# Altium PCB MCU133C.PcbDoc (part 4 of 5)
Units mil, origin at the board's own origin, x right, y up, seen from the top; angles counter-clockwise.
Board outline 2300 x 5500 mil, 4 copper layers (Top Signal, GND, PWR, Bottom Signal), stack 61.6 mil thick; 278 components, 226 nets, 1057 pads, 868 vias.
Unrouted connection lines stored in the file: 237.
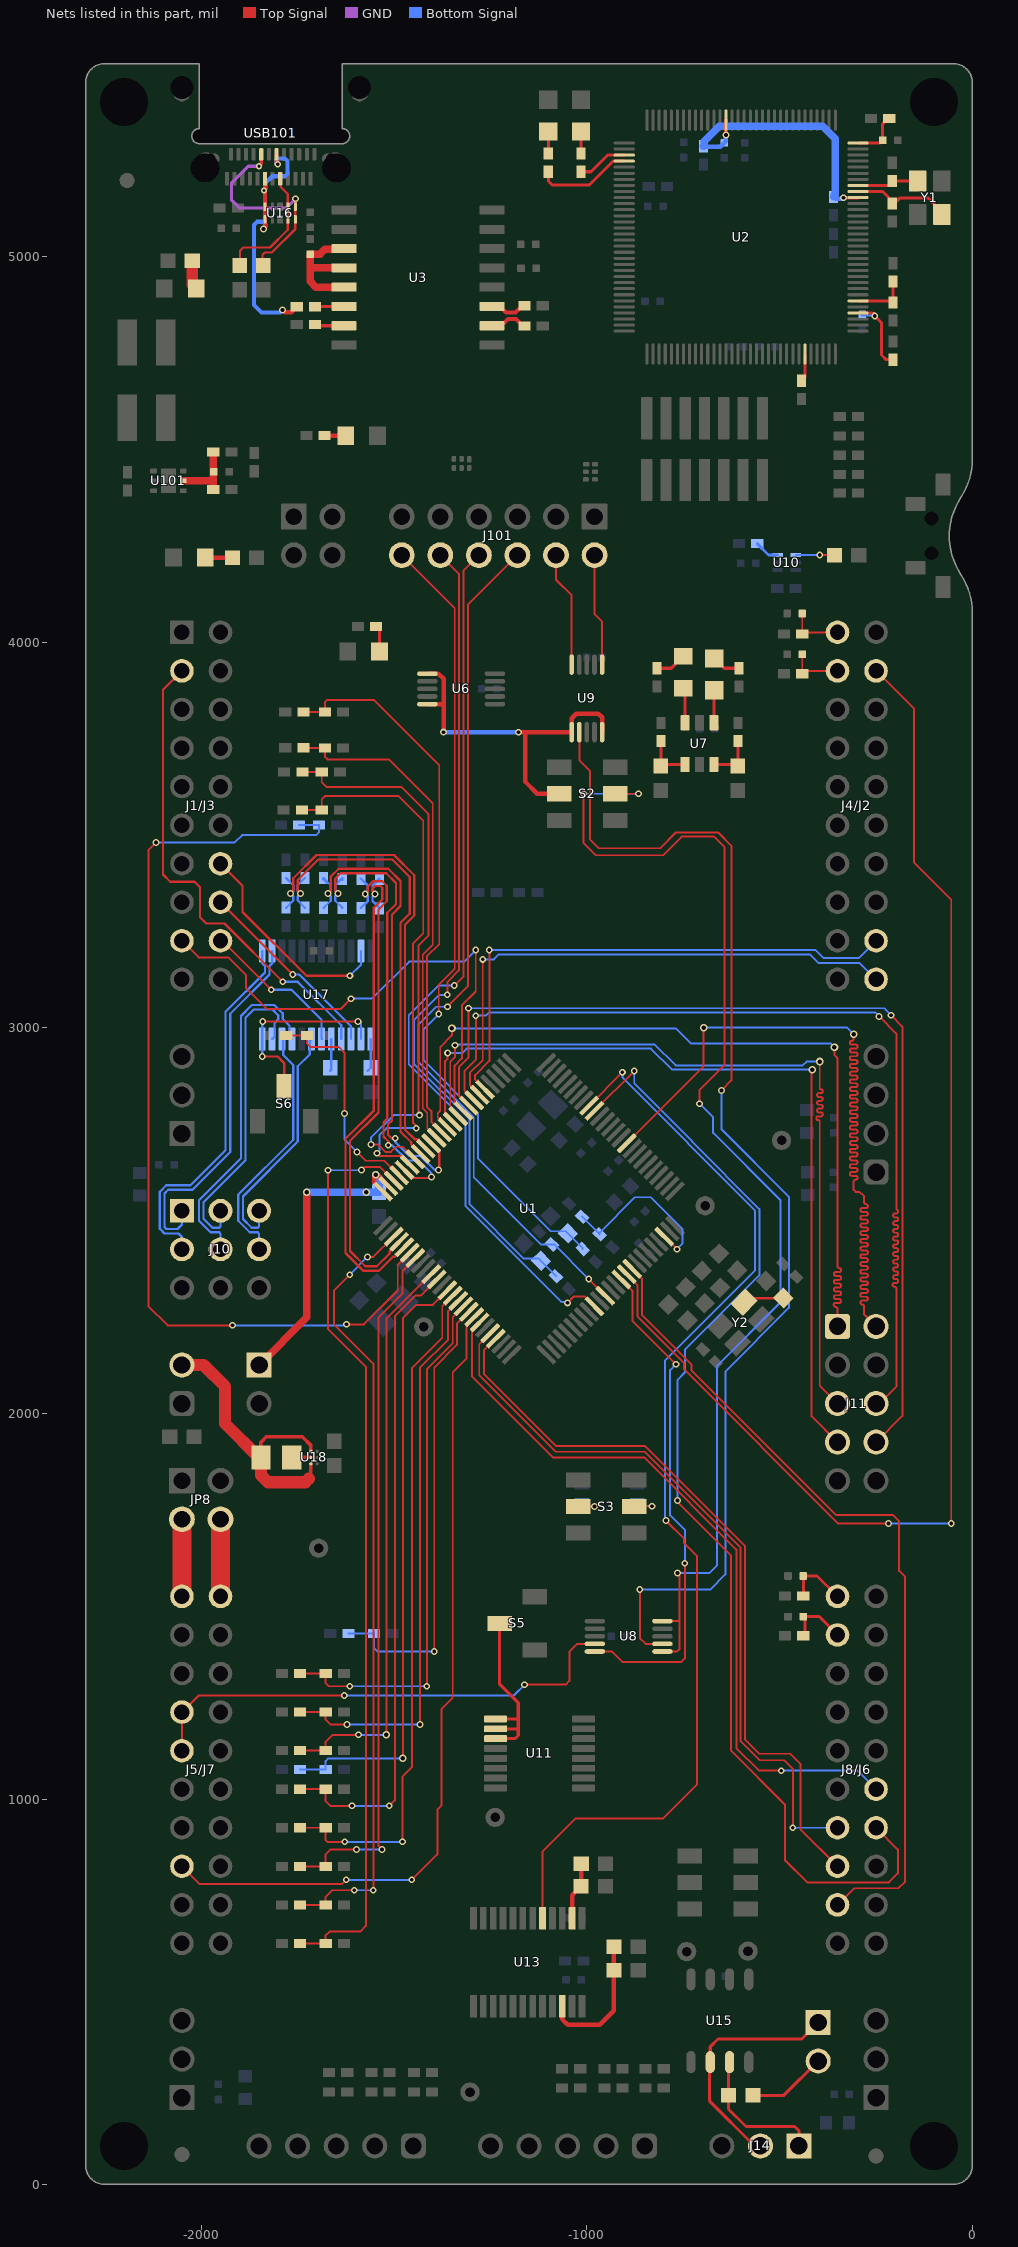
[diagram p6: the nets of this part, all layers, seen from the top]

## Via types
v1: diameter 17.72, hole 9.84, Top Signal to Bottom Signal, tented both sides, 822 vias
v2: diameter 19.68, hole 11.81, Top Signal to Bottom Signal, tented both sides, 22 vias
v3: diameter 27.56, hole 15.75, Top Signal to Bottom Signal, tented both sides, 17 vias
v4: diameter 15.75, hole 7.87, Top Signal to Bottom Signal, tented both sides, 5 vias
v5: diameter 19.68, hole 7.87, Top Signal to Bottom Signal, tented both sides, 2 vias

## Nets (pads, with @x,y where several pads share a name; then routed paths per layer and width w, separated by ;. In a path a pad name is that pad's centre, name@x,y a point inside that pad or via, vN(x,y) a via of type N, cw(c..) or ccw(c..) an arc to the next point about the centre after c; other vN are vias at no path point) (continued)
GPIO44_FSITXCLK: J11.2 U1.85 | length 2524.2
  Top Signal w5: U1.85@-896.72,2700.92 -697.04,2900.6 v2(-697.04,3000.55) ; v2(-308.04,2983.55) -308.04,2975.55 -308.04,2971.22 cw(c-313.04,2971.22) -313.04,2966.22 ccw(c-313.04,2961.22) -318.04,2961.22 ccw(c-313.04,2961.22) -313.04,2956.22 -308.04,2956.22 -303.04,2956.22 cw(c-303.04,2951.22) -298.04,2951.22 cw(c-303.04,2951.22) -303.04,2946.22 -308.04,2946.22 -313.04,2946.22 ccw(c-313.04,2941.22) -318.04,2941.22 ccw(c-313.04,2941.22) -313.04,2936.22 -308.04,2936.22 -303.04,2936.22 cw(c-303.04,2931.22) -298.04,2931.22 cw(c-303.04,2931.22) -303.04,2926.22 -308.04,2926.22 -313.04,2926.22 ccw(c-313.04,2921.22) -318.04,2921.22 ccw(c-313.04,2921.22) -313.04,2916.22 -308.04,2916.22 -303.04,2916.22 cw(c-303.04,2911.22) -298.04,2911.22 cw(c-303.04,2911.22) -303.04,2906.22 -308.04,2906.22 -313.04,2906.22 ccw(c-313.04,2901.22) -318.04,2901.22 ccw(c-313.04,2901.22) -313.04,2896.22 -308.04,2896.22 -303.04,2896.22 cw(c-303.04,2891.22) -298.04,2891.22 cw(c-303.04,2891.22) -303.04,2886.22 -308.04,2886.22 -313.04,2886.22 ccw(c-313.04,2881.22) -318.04,2881.22 ccw(c-313.04,2881.22) -313.04,2876.22 -308.04,2876.22 -303.04,2876.22 cw(c-303.04,2871.22) -298.04,2871.22 cw(c-303.04,2871.22) -303.04,2866.22 -308.04,2866.22 -313.04,2866.22 ccw(c-313.04,2861.22) -318.04,2861.22 ccw(c-313.04,2861.22) -313.04,2856.22 -308.04,2856.22 -303.04,2856.22 cw(c-303.04,2851.22) -298.04,2851.22 cw(c-303.04,2851.22) -303.04,2846.22 -308.04,2846.22 -313.04,2846.22 ccw(c-313.04,2841.22) -318.04,2841.22 ccw(c-313.04,2841.22) -313.04,2836.22 -308.04,2836.22 -303.04,2836.22 cw(c-303.04,2831.22) -298.04,2831.22 cw(c-303.04,2831.22) -303.04,2826.22 -308.04,2826.22 -313.04,2826.22 ccw(c-313.04,2821.22) -318.04,2821.22 ccw(c-313.04,2821.22) -313.04,2816.22 -308.04,2816.22 -303.04,2816.22 cw(c-303.04,2811.22) -298.04,2811.22 cw(c-303.04,2811.22) -303.04,2806.22 -308.04,2806.22 -313.04,2806.22 ccw(c-313.04,2801.22) -318.04,2801.22 ccw(c-313.04,2801.22) -313.04,2796.22 -308.04,2796.22 -303.04,2796.22 cw(c-303.04,2791.22) -298.04,2791.22 cw(c-303.04,2791.22) -303.04,2786.22 -308.04,2786.22 -313.04,2786.22 ccw(c-313.04,2781.22) -318.04,2781.22 ccw(c-313.04,2781.22) -313.04,2776.22 -308.04,2776.22 -303.04,2776.22 cw(c-303.04,2771.22) -298.04,2771.22 cw(c-303.04,2771.22) -303.04,2766.22 -308.04,2766.22 -313.04,2766.22 ccw(c-313.04,2761.22) -318.04,2761.22 ccw(c-313.04,2761.22) -313.04,2756.22 -308.04,2756.22 -303.04,2756.22 cw(c-303.04,2751.22) -298.04,2751.22 cw(c-303.04,2751.22) -303.04,2746.22 -308.04,2746.22 -313.04,2746.22 ccw(c-313.04,2741.22) -318.04,2741.22 ccw(c-313.04,2741.22) -313.04,2736.22 -308.04,2736.22 -303.04,2736.22 cw(c-303.04,2731.22) -298.04,2731.22 cw(c-303.04,2731.22) -303.04,2726.22 -308.04,2726.22 -313.04,2726.22 ccw(c-313.04,2721.22) -318.04,2721.22 ccw(c-313.04,2721.22) -313.04,2716.22 -308.04,2716.22 -303.04,2716.22 cw(c-303.04,2711.22) -298.04,2711.22 cw(c-303.04,2711.22) -303.04,2706.22 -308.04,2706.22 -313.04,2706.22 ccw(c-313.04,2701.22) -318.04,2701.22 ccw(c-313.04,2701.22) -313.04,2696.22 -308.04,2696.22 -303.04,2696.22 cw(c-303.04,2691.22) -298.04,2691.22 cw(c-303.04,2691.22) -303.04,2686.22 -308.04,2686.22 -313.04,2686.22 ccw(c-313.04,2681.22) -318.04,2681.22 ccw(c-313.04,2681.22) -313.04,2676.22 -308.04,2676.22 -303.04,2676.22 cw(c-303.04,2671.22) -298.04,2671.22 cw(c-303.04,2671.22) -303.04,2666.22 -308.04,2666.22 -313.04,2666.22 ccw(c-313.04,2661.22) -318.04,2661.22 ccw(c-313.04,2661.22) -313.04,2656.22 -308.04,2656.22 -303.04,2656.22 cw(c-303.04,2651.22) -298.04,2651.22 cw(c-303.04,2651.22) -303.04,2646.22 -308.04,2646.22 -313.04,2646.22 ccw(c-313.04,2641.22) -318.04,2641.22 ccw(c-313.04,2641.22) -313.04,2636.22 -308.04,2636.22 -303.04,2636.22 cw(c-303.04,2631.22) -298.04,2631.22 cw(c-303.04,2631.22) -303.04,2626.22 -308.04,2626.22 -313.04,2626.22 ccw(c-313.04,2621.22) -318.04,2621.22 ccw(c-313.04,2621.22) -313.04,2616.22 -308.04,2616.22 -303.04,2616.22 cw(c-303.04,2611.22) -298.04,2611.22 cw(c-303.04,2611.22) -303.04,2606.22 ccw(c-303.04,2601.22) -308.04,2601.22 -308.04,2596.22 -308.04,2591.22 -308.04,2579.55 -302.87,2574.39 -293.08,2574.39 -281.04,2563.55 -281.04,2547.55 ccw(c-276.04,2547.55) -276.04,2542.55 -276.19,2542.55 cw(c-276.2,2537.55) -271.2,2537.55 cw(c-276.2,2537.55) -276.2,2532.55 -281.04,2532.55 -285.88,2532.55 ccw(c-285.88,2527.55) -290.88,2527.55 ccw(c-285.88,2527.55) -285.88,2522.55 -281.04,2522.55 -276.2,2522.55 cw(c-276.2,2517.55) -271.2,2517.55 cw(c-276.2,2517.55) -276.2,2512.55 -281.04,2512.55 -285.88,2512.55 ccw(c-285.88,2507.55) -290.88,2507.55 ccw(c-285.88,2507.55) -285.88,2502.55 -281.04,2502.55 -276.2,2502.55 cw(c-276.2,2497.55) -271.2,2497.55 cw(c-276.2,2497.55) -276.2,2492.55 -281.04,2492.55 -285.88,2492.55 ccw(c-285.88,2487.55) -290.88,2487.55 ccw(c-285.88,2487.55) -285.88,2482.55 -281.04,2482.55 -276.2,2482.55 cw(c-276.2,2477.55) -271.2,2477.55 cw(c-276.2,2477.55) -276.2,2472.55 -281.04,2472.55 -285.88,2472.55 ccw(c-285.88,2467.55) -290.88,2467.55 ccw(c-285.88,2467.55) -285.88,2462.55 -281.04,2462.55 -276.2,2462.55 cw(c-276.2,2457.55) -271.2,2457.55 cw(c-276.2,2457.55) -276.2,2452.55 -281.04,2452.55 -285.88,2452.55 ccw(c-285.88,2447.55) -290.88,2447.55 ccw(c-285.88,2447.55) -285.88,2442.55 -281.04,2442.55 -276.2,2442.55 cw(c-276.2,2437.55) -271.2,2437.55 cw(c-276.2,2437.55) -276.2,2432.55 -281.04,2432.55 -285.88,2432.55 ccw(c-285.88,2427.55) -290.88,2427.55 ccw(c-285.88,2427.55) -285.88,2422.55 -281.04,2422.55 -276.2,2422.55 cw(c-276.2,2417.55) -271.2,2417.55 cw(c-276.2,2417.55) -276.2,2412.55 -281.04,2412.55 -285.88,2412.55 ccw(c-285.88,2407.55) -290.88,2407.55 ccw(c-285.88,2407.55) -285.88,2402.55 -281.04,2402.55 -276.2,2402.55 cw(c-276.2,2397.55) -271.2,2397.55 cw(c-276.2,2397.55) -276.2,2392.55 -281.04,2392.55 -285.88,2392.55 ccw(c-285.88,2387.55) -290.88,2387.55 ccw(c-285.88,2387.55) -285.88,2382.55 -281.04,2382.55 -276.2,2382.55 cw(c-276.2,2377.55) -271.2,2377.55 cw(c-276.2,2377.55) -276.2,2372.55 -281.04,2372.55 -285.88,2372.55 ccw(c-285.88,2367.55) -290.88,2367.55 ccw(c-285.88,2367.55) -285.88,2362.55 -281.04,2362.55 -276.2,2362.55 cw(c-276.2,2357.55) -271.2,2357.55 cw(c-276.2,2357.55) -276.2,2352.55 -281.04,2352.55 -285.88,2352.55 ccw(c-285.88,2347.55) -290.88,2347.55 ccw(c-285.88,2347.55) -285.88,2342.55 -281.04,2342.55 -276.2,2342.55 cw(c-276.2,2337.55) -271.2,2337.55 cw(c-276.2,2337.55) -276.2,2332.55 -281.04,2332.55 -285.88,2332.55 ccw(c-285.88,2327.55) -290.88,2327.55 ccw(c-285.88,2327.55) -285.88,2322.55 -281.04,2322.55 -276.2,2322.55 cw(c-276.2,2317.55) -271.2,2317.55 cw(c-276.2,2317.55) -276.2,2312.55 -281.04,2312.55 -285.88,2312.55 ccw(c-285.88,2307.55) -290.88,2307.55 ccw(c-285.88,2307.55) -285.88,2302.55 -281.04,2302.55 -276.2,2302.55 cw(c-276.2,2297.55) -271.2,2297.55 cw(c-276.2,2297.55) -276.2,2292.55 -281.04,2292.55 -286.04,2292.55 ccw(c-286.04,2287.55) -291.04,2287.55 ccw(c-286.04,2287.55) -286.04,2282.55 cw(c-286.04,2277.55) -281.04,2277.55 -281.04,2272.55 -281.04,2262.55 -281.04,2257.55 -281.04,2256.55 J11.2@-250.04,2225.55
  Bottom Signal w5: v2(-697.04,3000.55) -325.04,3000.55 v2(-308.04,2983.55)
GPIO47: J4/J2.12 U1.6 | length 1417
  Top Signal w5: U1.6@-1264.2,2840.11 -1289.8,2865.72 -1289.8,2877.41 -1252.78,2914.44 -1252.78,3201.29 v1(-1253.04,3201.55)
  Bottom Signal w5: v1(-1253.04,3201.55) -407.04,3201.55 -387.04,3181.55 -294.04,3181.55 J4/J2.12@-250.04,3225.55
GPIO48: J4/J2.11 U1.7 | length 1427.8
  Top Signal w5: U1.7@-1278.12,2826.19 -1303.17,2851.25 -1303.17,2882.92 -1270.04,2916.05 v1(-1270.04,3177.55)
  Bottom Signal w5: v1(-1270.04,3177.55) -1241.04,3177.55 -1227.94,3190.65 -422.13,3190.65 -400.04,3168.55 -293.04,3168.55 J4/J2.11@-250.04,3125.55
GPIO49_FSITXD0: J11.6 U1.8 | length 2525.5
  Top Signal w5: U1.8@-1292.04,2812.27 -1316.81,2837.05 -1316.81,2888.43 -1288,2917.24 v1(-1288,3031.42) ; J11.6@-250.04,2025.55 -241.54,2025.55 -197.28,2069.8 -197.28,2323.53 ccw(c-202.28,2323.53) -202.28,2328.53 cw(c-202.28,2333.53) -207.28,2333.53 cw(c-202.28,2333.53) -202.28,2338.53 -197.28,2338.53 ccw(c-197.28,2343.18) -192.64,2343.18 -192.64,2343.88 ccw(c-197.28,2343.88) -197.28,2348.53 -200.79,2348.53 cw(c-200.79,2353.53) -205.79,2353.53 cw(c-200.79,2353.53) -200.79,2358.53 -197.28,2358.53 ccw(c-197.28,2363.18) -192.64,2363.18 -192.64,2363.88 ccw(c-197.28,2363.88) -197.28,2368.53 -200.79,2368.53 cw(c-200.79,2373.53) -205.79,2373.53 cw(c-200.79,2373.53) -200.79,2378.53 -197.28,2378.53 ccw(c-197.28,2383.18) -192.64,2383.18 -192.64,2383.88 ccw(c-197.28,2383.88) -197.28,2388.53 -200.79,2388.53 cw(c-200.79,2393.53) -205.79,2393.53 cw(c-200.79,2393.53) -200.79,2398.53 -197.28,2398.53 ccw(c-197.28,2403.18) -192.64,2403.18 -192.64,2403.88 ccw(c-197.28,2403.88) -197.28,2408.53 -200.79,2408.53 cw(c-200.79,2413.53) -205.79,2413.53 cw(c-200.79,2413.53) -200.79,2418.53 -197.28,2418.53 ccw(c-197.28,2423.18) -192.64,2423.18 -192.64,2423.88 ccw(c-197.28,2423.88) -197.28,2428.53 -200.79,2428.53 cw(c-200.79,2433.53) -205.79,2433.53 cw(c-200.79,2433.53) -200.79,2438.53 -197.28,2438.53 ccw(c-197.28,2443.18) -192.64,2443.18 -192.64,2443.88 ccw(c-197.28,2443.88) -197.28,2448.53 -200.79,2448.53 cw(c-200.79,2453.53) -205.79,2453.53 cw(c-200.79,2453.53) -200.79,2458.53 -197.28,2458.53 ccw(c-197.28,2463.18) -192.64,2463.18 -192.64,2463.88 ccw(c-197.28,2463.88) -197.28,2468.53 -200.79,2468.53 cw(c-200.79,2473.53) -205.79,2473.53 cw(c-200.79,2473.53) -200.79,2478.53 -197.28,2478.53 ccw(c-197.28,2483.18) -192.64,2483.18 -192.64,2483.88 ccw(c-197.28,2483.88) -197.28,2488.53 -200.79,2488.53 cw(c-200.79,2493.53) -205.79,2493.53 cw(c-200.79,2493.53) -200.79,2498.53 -197.28,2498.53 ccw(c-197.28,2503.18) -192.64,2503.18 -192.64,2503.88 ccw(c-197.28,2503.88) -197.28,2508.53 -200.79,2508.53 cw(c-200.79,2513.53) -205.79,2513.53 cw(c-200.79,2513.53) -200.79,2518.53 -197.28,2518.53 ccw(c-197.28,2523.18) -192.64,2523.18 -192.64,2523.88 ccw(c-197.28,2523.88) -197.28,2528.53 -197.28,2544.55 -197.28,2984.8 v1(-242.04,3029.55)
  Bottom Signal w5: v1(-1288,3031.42) -1261.77,3031.42 -1253.37,3039.82 -252.3,3039.82 v1(-242.04,3029.55)
GPIO50_FSITXD1: J11.8 U1.9 | length 2523.7
  Top Signal w5: v1(-1307.04,3050.72) -1307.04,2922.52 -1331.04,2898.52 -1331.04,2823.44 U1.9@-1305.96,2798.35 ; J11.8@-250.04,1925.55 -181.73,1993.86 -181.73,3003.24 v1(-211.04,3032.55)
  Bottom Signal w5: v1(-1307.04,3050.72) -229.21,3050.72 v1(-211.04,3032.55)
GPIO51: J1/J3.9 U1.10 | length 1367.9
  Top Signal w5: J1/J3.9@-2050.04,3225.55 -2007.04,3182.55 -1929.62,3182.55 -1884.13,3137.07 -1884.13,3103.65 -1829.04,3048.55 -1638.85,3048.55 v1(-1611.95,3075.45) ; U1.10@-1319.87,2784.43 -1343.17,2807.73 -1343.17,2901.81 -1324.3,2920.68 -1324.3,3057.87 -1288.04,3094.14 v1(-1288.04,3201.55)
  Bottom Signal w5: v1(-1611.95,3075.45) -1557.22,3075.45 -1461.13,3171.55 -1318.04,3171.55 v1(-1288.04,3201.55)
GPIO52_FSIRXD0: J11.5 U1.11 | length 2163.9
  Top Signal w5: v1(-1342.04,2954.55) -1342.04,2923.88 -1354.21,2911.71 -1354.21,2790.93 U1.11@-1333.79,2770.51 ; v2(-396.04,2912.55) -396.04,2844.29 ccw(c-392.3,2844.29) -392.3,2840.55 ; -393.15,2840.55 cw(c-393.15,2835.55) -388.15,2835.55 cw(c-393.15,2835.55) -393.15,2830.55 -396.04,2830.55 -398.03,2830.55 ccw(c-398.03,2825.55) -403.03,2825.55 ccw(c-398.03,2825.55) -398.03,2820.55 -396.04,2820.55 -393.15,2820.55 cw(c-393.15,2815.55) -388.15,2815.55 cw(c-393.15,2815.55) -393.15,2810.55 -396.04,2810.55 -398.03,2810.55 ccw(c-398.03,2805.55) -403.03,2805.55 ccw(c-398.03,2805.55) -398.03,2800.55 -396.04,2800.55 -393.15,2800.55 cw(c-393.15,2795.55) -388.15,2795.55 cw(c-393.15,2795.55) -393.15,2790.55 -396.04,2790.55 -398.03,2790.55 ccw(c-398.03,2785.55) -403.03,2785.55 ccw(c-398.03,2785.55) -398.03,2780.55 -396.04,2780.55 -393.15,2780.55 cw(c-393.15,2775.55) -388.15,2775.55 cw(c-393.15,2775.55) -393.15,2770.55 -396.04,2770.55 -400.14,2770.55 ccw(c-400.14,2765.55) -405.14,2765.55 ccw(c-400.14,2765.55) -400.14,2760.55 cw(c-400.14,2756.45) -396.04,2756.45 -396.04,2755.55 -396.04,2071.55 J11.5@-350.04,2025.55
  Bottom Signal w5: v1(-1342.04,2954.55) -1339.46,2957.13 -824.71,2957.13 -770.05,2902.46 -440.45,2902.46 -430.36,2912.55 v2(-396.04,2912.55)
GPIO53_FSIRXD1: J11.7 U1.12 | length 2166.6
  Top Signal w5: v1(-1360.96,2934.51) -1360.96,2920.38 -1367.84,2913.5 -1367.84,2776.72 -1360.96,2769.85 U1.12@-1347.71,2756.6 ; v2(-416.04,2891.55) -416.94,2890.65 -416.94,1992.45 J11.7@-350.04,1925.55 J11.7@-361.06,1925.55
  Bottom Signal w5: v1(-1360.96,2934.51) -1323.37,2934.55 -1311.7,2946.22 -833.86,2946.22 -779.19,2891.55 v2(-416.04,2891.55)
GPIO54_FSIRXCLK: J11.1 U1.13 | length 2165.3
  Top Signal w5: U1.13@-1361.63,2742.68 -1386.75,2767.79 -1386.75,2779.02 -1380.22,2785.56 -1380.22,2949.79 -1349.8,2980.2 v2(-1349.8,2998.55) ; v2(-357.91,2949.96) -357.91,2931.88 -357.7,2931.66 -357.7,2929.18 -350.04,2921.52 -350.04,2382.24 -350.04,2381.55 ccw(c-345.04,2381.55) -345.04,2376.55 ; J11.1@-350.04,2225.55 -350.04,2271.55 ccw(c-355.04,2271.55) -355.04,2276.55 cw(c-355.04,2281.55) -360.04,2281.55 cw(c-355.04,2281.55) -355.04,2286.55 -350.04,2286.55 -345.58,2286.55 ccw(c-345.58,2291.55) -340.58,2291.55 ccw(c-345.58,2291.55) -345.58,2296.55 -350.04,2296.55 -354.5,2296.55 cw(c-354.5,2301.55) -359.5,2301.55 cw(c-354.5,2301.55) -354.5,2306.55 -350.04,2306.55 -345.58,2306.55 ccw(c-345.58,2311.55) -340.58,2311.55 ccw(c-345.58,2311.55) -345.58,2316.55 -350.04,2316.55 -354.5,2316.55 cw(c-354.5,2321.55) -359.5,2321.55 cw(c-354.5,2321.55) -354.5,2326.55 -350.04,2326.55 -345.58,2326.55 ccw(c-345.58,2331.55) -340.58,2331.55 ccw(c-345.58,2331.55) -345.58,2336.55 -350.04,2336.55 -354.5,2336.55 cw(c-354.5,2341.55) -359.5,2341.55 cw(c-354.5,2341.55) -354.5,2346.55 -350.04,2346.55 -345.58,2346.55 ccw(c-345.58,2351.55) -340.58,2351.55 ccw(c-345.58,2351.55) -345.58,2356.55 -350.04,2356.55 -354.5,2356.55 cw(c-354.5,2361.55) -359.5,2361.55 cw(c-354.5,2361.55) -354.5,2366.55 -350.04,2366.55 -345.58,2366.55 ccw(c-345.58,2371.55) -340.58,2371.55 ccw(c-345.58,2371.55) -345.58,2376.55 ; -345.52,2376.55 -345.09,2376.55
  Bottom Signal w5: v2(-1349.8,2998.55) -769.22,2998.55 -729.72,2959.05 -367,2959.05 v2(-357.91,2949.96)
GPIO55: J5/J7.48 U1.43 | length 2146.1
  Top Signal w5: J5/J7.48@-2050.04,825.55 -2004.04,779.55 -1635.04,779.55 v1(-1624.04,790.55) ; v1(-1454.04,790.55) -1387.83,856.76 -1387.83,972.6 -1376.52,983.92 -1376.52,1233.59 -1347.68,1262.43 -1347.68,2106.76 -1312.16,2142.27 -1312.16,2229.8 U1.43@-1292.04,2249.93
  Bottom Signal w5: v1(-1624.04,790.55) v1(-1454.04,790.55)
GPIO56: U1.65 U8.10 | length 1311.4
  Top Signal w5: U8.10@-979.15,1382.7 -934.89,1382.7 -907.86,1355.67 -754.92,1355.67 -746.04,1364.55 v1(-746.04,1611.55) ; U1.65@-910.64,2347.36 -882.04,2318.76 -882.04,2240.55 v1(-769.04,2127.55)
  Bottom Signal w5: v1(-769.04,2127.55) -784.04,2112.55 -784.04,1735.86 -746.04,1697.86 v1(-746.04,1611.55)
GPIO56_BP: J5/J7.44 J5/J7.45 U8.9 | length 1288.4
  Top Signal w5: J5/J7.45@-2050.04,1125.55 J5/J7.44@-2050.04,1225.55 -2007.04,1268.55 v1(-1629.04,1268.55) ; v1(-1161.54,1296.55) -1055.04,1296.55 -1045.27,1306.32 -1045.27,1381.82 -1024.7,1402.39 U8.9@-979.15,1402.39
  Bottom Signal w5: v1(-1629.04,1268.55) -1189.54,1268.55 v1(-1161.54,1296.55)
GPIO56_SCITX: U8.2 U9.2 | length 3166.6
  Top Signal w5: U9.2@-1019.61,3766.68 -1019.61,3693.91 -991.38,3665.67 -991.38,3488.01 -968.92,3465.55 -810.11,3465.55 -769.19,3506.48 -659.9,3506.48 -624.97,3471.55 -624.97,2863.59 v1(-650.78,2837.79) ; v1(-862.62,1543.3) -862.62,1417.14 -847.87,1402.39 U8.2@-803.95,1402.39
  Bottom Signal w5: v1(-862.62,1543.3) -680.47,1543.3 -640.96,1582.8 -640.96,2108.63 -476.04,2273.55 -476.04,2561.55 -650.78,2736.29 v1(-650.78,2837.79)
GPIO57: J4/J2.19 U1.66 | length 3458.7
  Top Signal w5: U1.66@-896.72,2361.28 -868.89,2333.44 -868.89,2251.81 -747.62,2130.55 -747.62,2114.29 -347.88,1714.55 v1(-217.91,1714.55) ; J4/J2.19@-250.04,3925.55 -151.36,3826.87 -151.36,3427.93 -55.04,3331.61 v1(-55.04,1714.55)
  Bottom Signal w5: v1(-217.91,1714.55) v1(-55.04,1714.55)
GPIO58: J8/J6.72 U1.67 | length 2169.4
  Top Signal w5: U1.67@-882.8,2375.2 -857.13,2349.52 -857.13,2255.48 -728.39,2126.74 -728.39,2111.06 -354.39,1737.07 -206.63,1737.07 -190.15,1720.59 -190.15,1591.85 -174.84,1576.54 -174.84,785.69 -191.87,768.66 -306.93,768.66 J8/J6.72@-350.04,725.55
GPIO59: U1.92 U13.5 | length 2889.5
  Top Signal w5: U13.5@-1114.92,692.99 -1114.92,864.17 -1029.54,949.55 -803.04,949.55 -714.04,1038.55 -714.04,1629.55 -748.04,1663.55 -748.04,1675.45 v1(-794.78,1722.18) v1@-794.78,1727.29 ; U1.92@-994.16,2798.35 v1(-907.96,2884.55)
  Bottom Signal w5: v1(-907.96,2884.55) -907.96,2871.58 -738.02,2701.64 -738.02,2700.15 -564.33,2526.46 -564.33,2370.51 -797.04,2137.8 v1@-797.04,1722.18
GPIO60: J8/J6.55 U1.44 | length 1941.3
  Top Signal w5: U1.44@-1278.12,2236.01 -1298.24,2215.88 -1298.24,2096.39 -1087.25,1885.39 -850.46,1885.39 -612.11,1647.05 -612.11,1132.2 -553.46,1073.55 v1(-496.04,1073.55)
  Bottom Signal w5: v1(-496.04,1073.55) -298.04,1073.55 J8/J6.55@-250.04,1025.55
GPIO61: J8/J6.54 U1.91 | length 2998.9
  Top Signal w5: U1.91@-980.24,2784.43 v1(-877.04,2887.64) ; v1@-767.16,1772.67 -626.71,1632.22 -626.71,1126.22 -486.18,985.69 -486.18,841.69 -428.41,783.92 -216.67,783.92 -193.54,807.05 -193.54,869.05 J8/J6.54@-250.04,925.55
  Bottom Signal w5: v1(-877.04,2887.64) -877.04,2856.08 -727.11,2706.15 -727.11,2704.67 -552.38,2529.93 -552.38,2357.92 -745.65,2164.65 -745.65,2106.16 -765.16,2086.65 v1(-765.16,1774.55) ; v1@-767.27,1772.67 v1@-767.27,1774.55
GPIO62: J8/J6.74 U1.46 | length 1919.6
  Top Signal w5: U1.46@-1250.28,2208.17 -1279.04,2179.41 -1279.04,2099.55 -1080.04,1900.55 -849.46,1900.55 -601.21,1652.3 -601.21,1150.3 -551.46,1100.55 -488.04,1100.55 -465.98,1078.5 -465.98,925.61 v1(-466.04,925.55)
  Bottom Signal w5: v1(-466.04,925.55) J8/J6.74@-350.04,925.55
GPIO63: J8/J6.73 U1.47 | length 1943.4
  Top Signal w5: U1.47@-1236.36,2194.25 -1266.98,2163.63 -1266.98,2102.99 -1079.37,1915.38 -848.87,1915.38 -590.3,1656.82 -590.3,1154.82 -553.04,1117.55 -472.54,1117.55 -446.04,1091.05 -446.04,921.55 J8/J6.73@-350.04,825.55
MCU_A0/B15/C15/DACA_OUT: C25.1 R12.2 U1.23 | length 2390.2
  Top Signal w5: R12.2@-1743.69,625.55 C25.1@-1677.28,625.55 -1677.28,646.31 -1667.23,656.36 -1587.62,656.36 -1573.04,670.94 -1573.04,2120.55 -1671.04,2218.55 v1(-1671.04,2630.55) ; v1(-1584.43,2631) -1576.45,2638.98 -1536.32,2638.98 U1.23@-1500.83,2603.48
  Bottom Signal w5: v1(-1671.04,2630.55) -1584.88,2630.55 v1(-1584.43,2631)
MCU_A1/B7/D11/DACB_OUT: C33.1 R13.2 U1.22 | length 587.4
  Top Signal w5: R13.2@-1779.6,2980.24 C33.1@-1725.66,2980.24 -1725.66,2958.61 -1717.6,2950.55 -1643.7,2950.55 -1628.7,2935.55 v1@-1628.7,2777.62 ; v1(-1595.91,2677.82) -1573.35,2655.26 -1524.77,2655.26 U1.22@-1486.91,2617.4
  Bottom Signal w5: v1@-1628.7,2777.62 -1628.7,2710.61 v1(-1595.91,2677.82)
  other v1: -1628.68,2777.62
MCU_A4/B8: C27.1 R16.2 U1.36 | length 1691.2
  Top Signal w5: R16.2@-1743.69,1025.55 C27.1@-1677.28,1025.55 -1677.28,994.44 -1665.39,982.55 v1(-1609.04,982.55) ; v1(-1512.24,982.55) -1498.04,996.75 -1498.04,2252.55 -1444.98,2305.61 -1431.23,2305.61 U1.36@-1389.47,2347.36
  Bottom Signal w5: v1(-1609.04,982.55) v1(-1512.24,982.55)
MCU_A5: C35.1 R17.2 U1.35 | length 1497.8
  Top Signal w5: R17.2@-1743.69,1125.55 C35.1@-1677.28,1125.55 -1677.28,1148.31 -1659.04,1166.55 v1(-1592.04,1166.55) ; v2(-1520.04,1166.55) -1520.04,2245.97 -1404.73,2361.28 U1.35@-1403.39,2361.28
  Bottom Signal w5: v1(-1592.04,1166.55) v2(-1520.04,1166.55)
MCU_A6/D14/E14: C28.1 R18.2 U1.14 | length 1431.5
  Top Signal w5: R18.2@-1735.04,3818.85 C28.1@-1679.29,3818.85 -1679.29,3843.97 -1672.91,3850.35 -1552.83,3850.35 -1382.72,3680.23 -1382.72,3216.99 -1414.74,3184.96 -1414.74,2795.88 -1402.93,2784.06 -1402.93,2756.13 U1.14@-1375.55,2728.76
MCU_A7/B30/C3/D12/E30: C36.1 R19.2 U1.31 | length 2529.1
  Top Signal w5: v1(-2117.04,3480.55) -2137.04,3460.55 -2137.04,2278.55 -2087.04,2228.55 v1(-1919.04,2228.55) ; v1(-1623.04,2231.08) -1578.03,2231.08 -1490.33,2318.78 -1490.33,2385.7 U1.31@-1459.07,2416.96
  Bottom Signal w5: v1(-2117.04,3480.55) -1913.03,3480.55 -1893.92,3499.67 -1702.01,3499.67 -1695.04,3506.63 C36.1@-1695.04,3525.55 R19.2@-1746.21,3525.55 ; v1(-1919.04,2228.55) -1625.57,2228.55 v1(-1623.04,2231.08)
MCU_A9: C29.1 R20.2 U1.38 | length 1578.2
  Top Signal w5: v2(-1477.04,1105.55) -1477.04,2246.88 -1442.26,2281.66 -1399.5,2281.66 U1.38@-1361.63,2319.53
  Bottom Signal w5: R20.2@-1743.69,1076.55 C29.1@-1677.28,1076.55 -1677.28,1098.31 -1670.04,1105.55 v2(-1477.04,1105.55)
MCU_A10/B1/C10: C37.1 R21.2 U1.40 | length 1474.7
  Top Signal w5: R21.2@-1743.69,1225.55 C37.1@-1677.28,1225.55 -1677.28,1205.8 -1665.04,1193.55 v1(-1622.04,1193.55) ; v1(-1433.04,1193.55) -1433.04,2118.61 -1360.04,2191.61 -1360.04,2265.44 U1.40@-1333.79,2291.69
  Bottom Signal w5: v1(-1622.04,1193.55) v1(-1433.04,1193.55)
MCU_A11/B10/C0/PGA2_OUT: C30.1 R22.2 U1.20 | length 1421.8
  Top Signal w5: R22.2@-1733.38,3564.92 C30.1@-1687.45,3564.92 -1687.45,3592.51 -1679.04,3600.92 -1488.04,3600.92 -1424.25,3537.13 -1424.25,3244.82 -1450.96,3218.1 -1450.96,2754.43 v1@-1442.46,2745.93 ; v1(-1544.04,2674.55) -1536.77,2667.29 -1481.12,2667.29 U1.20@-1459.07,2645.24
  Bottom Signal w5: v1(-1544.04,2674.55) -1537.82,2680.77 -1537.82,2721.14 -1519.23,2739.72 v1(-1442.46,2739.72)
MCU_A12/C5: C38.1 R23.2 U1.28 | length 2028.8
  Top Signal w5: R23.2@-1743.69,725.55 C38.1@-1677.28,725.55 -1677.28,746.52 -1660.25,763.55 v1(-1603.04,763.55) ; v1(-1615.04,2359.66) -1656.04,2318.66 -1656.04,2231.55 -1553.72,2129.23 v1(-1553.72,763.55) ; v1(-1569.04,2405.83) -1553.72,2405.83 U1.28@-1500.83,2458.72
  Bottom Signal w5: v1(-1615.04,2359.66) -1615.04,2359.83 v1(-1569.04,2405.83) ; v1(-1603.04,763.55) v1(-1553.72,763.55)
MCU_A14/B14/C4/PGA1_OUT: C31.1 R24.2 U1.19 | length 1489.7
  Top Signal w5: R24.2@-1737.68,3662.93 C31.1@-1687.45,3662.93 -1687.45,3636.82 -1674.72,3624.09 -1480.45,3624.09 -1410.47,3554.11 -1410.47,3240.01 -1436.55,3213.93 -1436.55,2776.34 v1(-1433.7,2773.48) ; v1(-1560.04,2697.55) -1541.64,2697.55 -1522.29,2678.19 -1507.98,2678.19 -1494.61,2691.57 -1477.56,2691.57 U1.19@-1445.15,2659.16
  Bottom Signal w5: v1(-1560.04,2697.55) -1560.04,2714.34 -1500.89,2773.48 v1(-1433.7,2773.48)
MCU_B0/C11: C107.1 R109.2 U1.41 | length 1381.7
  Top Signal w5: C107.1@-1677.28,1325.55 -1677.28,1300.44 -1669.39,1292.55 v1(-1615.04,1292.55) ; v1(-1415.04,1292.55) -1415.04,2115.12 -1347.85,2182.31 -1347.85,2249.79 U1.41@-1319.87,2277.77
  Top Signal w5.91: R109.2@-1743.69,1325.55 C107.1@-1677.28,1325.55
  Bottom Signal w5: v1(-1615.04,1292.55) v1(-1415.04,1292.55)
MCU_B2/C6/E12: C39.1 R25.2 U1.15 | length 1301
  Top Signal w5: R25.2@-1734.8,3726.18 -1734.17,3725.55 C39.1@-1679.37,3725.55 -1679.37,3702.91 -1672.38,3695.93 -1513.72,3695.93 -1399.57,3581.77 -1399.57,3215.56 -1425.65,3189.48 -1425.65,2791.36 -1413.83,2779.54 -1413.83,2739.2 U1.15@-1389.47,2714.84
MCU_B4/C8: C40.1 R27.2 U1.39 | length 1769.8
  Top Signal w5: R27.2@-1743.69,925.55 C40.1@-1677.28,925.55 -1677.28,893.8 -1672.68,889.19 v1(-1628.04,889.19) ; v1(-1477.89,889.19) -1477.89,1058.7 -1453.04,1083.55 -1453.04,2118.01 -1375.04,2196.01 -1375.04,2278.28 U1.39@-1347.71,2305.61
  Bottom Signal w5: v1(-1628.04,889.19) v1(-1477.89,889.19)
MCU_B5/D15/E15/PGA3_OUT: C75.1 R84.2 U1.32 | length 1825.6
  Top Signal w5: R84.2@-1743.69,825.55 C75.1@-1677.28,825.55 -1677.28,856.69 -1664.43,869.55 v1(-1597.04,869.55) ; v1(-1531.04,869.55) -1540.04,878.55 -1540.04,918.55 -1540.04,2233.55 -1540.04,2248.95 -1477.79,2311.2 -1477.79,2370.41 U1.32@-1445.15,2403.04
  Bottom Signal w5: v1(-1597.04,869.55) v1(-1531.04,869.55)
MCU_C14: C108.1 R110.2 U1.42 | length 1182.7
  Top Signal w5: v1(-1395.74,1382.3) -1395.74,2118.73 -1336.95,2177.52 -1336.95,2232.85 U1.42@-1305.96,2263.85
  Bottom Signal w5: C108.1@-1551.78,1429.3 -1551.78,1391.7 -1542.39,1382.3 v1(-1395.74,1382.3)
  Bottom Signal w5.91: R110.2@-1618.19,1429.3 C108.1@-1551.78,1429.3
MCU_PGA1_IN_N: C34.1 R15.2 U1.18 | length 1215.4
  Top Signal w5.91: v1(-1742.72,3348.43) -1749.61,3355.32 -1749.61,3382.98 -1696.41,3436.18 -1504.73,3436.18 -1459.29,3390.74 -1459.29,3296.09 -1483.11,3272.27 -1483.11,2730.53 -1455.59,2703.01 -1455.59,2697.44 U1.18@-1431.23,2673.08
  Bottom Signal w5.91: C34.1@-1731.34,3388.51 -1749.61,3370.24 -1749.61,3355.32 v1(-1742.72,3348.43) -1749.61,3341.54 -1749.61,3329.94 R15.2@-1731.26,3311.6
MCU_PGA1_IN_P: C26.1 R14.2 U1.17 | length 1244.8
  Top Signal w5.91: v1(-1768.31,3348.43) -1761.42,3355.32 -1761.42,3387.87 -1701.3,3447.99 -1499.84,3447.99 -1447.48,3395.63 -1447.48,3291.2 -1471.3,3267.38 -1471.3,2735.42 -1447.24,2711.36 -1441.67,2711.36 U1.17@-1417.31,2687
  Bottom Signal w5.91: C26.1@-1779.95,3388.43 -1761.42,3369.9 -1761.42,3355.32 v1(-1768.31,3348.43) -1761.42,3341.54 -1761.42,3329.94 R14.2@-1779.76,3311.6
MCU_PGA2_IN_N: C76.1 R86.2 U1.21 | length 1245.5
  Top Signal w5.91: v1(-1645.41,3348.16) -1652.3,3355.05 -1652.3,3387.29 -1638.66,3400.93 -1520.17,3400.93 -1494.82,3375.58 -1494.82,3320.6 -1517.36,3298.06 -1517.36,2764.7 -1527.42,2754.64 -1527.42,2717.95 -1515.13,2705.67 v1(-1515.13,2695.46) ; U1.21@-1472.99,2631.32 -1452.41,2610.74 -1405.24,2610.74 v1(-1403.07,2612.91)
  Bottom Signal w5.91: C76.1@-1634.34,3383.9 C76.1@-1634.34,3386.01 ; C76.1@-1634.03,3388.25 -1652.3,3369.98 -1652.3,3355.05 v1(-1645.41,3348.16) -1652.3,3341.27 -1652.3,3329.68 R86.2@-1633.96,3311.33 ; v1(-1515.13,2695.46) -1505.24,2695.46 -1465.4,2655.61 -1436.03,2655.61 -1403.07,2622.65 v1(-1403.07,2612.91)
MCU_PGA2_IN_P: C32.1 R26.2 U1.16 | length 1288
  Top Signal w5.91: v1(-1671,3348.16) -1664.11,3355.05 -1664.11,3392.18 -1643.55,3412.74 -1515.28,3412.74 -1483.01,3380.47 -1483.01,3315.71 -1505.55,3293.17 -1505.55,2759.8 -1515.61,2749.75 -1515.61,2722.84 -1506.32,2713.55 v1(-1497.04,2713.55) ; U1.16@-1403.39,2700.92 -1382.81,2680.34 -1382.81,2633.16 v1(-1384.98,2631)
  Bottom Signal w5.91: C32.1@-1683.26,3388.35 -1683.26,3385.27 C32.1@-1674.41,3376.42 ; C32.1@-1682.64,3388.17 -1664.11,3369.64 -1664.11,3355.05 v1(-1671,3348.16) -1664.11,3341.27 -1664.11,3329.68 R26.2@-1682.46,3311.33 ; v1(-1497.04,2713.55) -1497.04,2703.96 -1460.51,2667.42 -1431.14,2667.42 -1394.72,2631 v1(-1384.98,2631)
MCU_PGA3_IN_N: C77.1 R85.2 U1.30 | length 1329.2
  Top Signal w5.91: v1(-1549.14,3347.25) -1556.03,3354.14 -1556.03,3361.42 -1549.48,3367.97 -1535.18,3367.97 -1530.45,3363.25 -1530.45,3332.9 -1552.3,3311.05 -1552.3,2785.56 -1625.85,2712.01 -1625.85,2416.13 -1579.38,2369.66 -1539.78,2369.66 -1502.91,2406.52 -1497.35,2406.52 U1.30@-1472.99,2430.88
  Bottom Signal w5.91: C77.1@-1537.76,3387.34 -1556.03,3369.06 -1556.03,3354.14 v1(-1549.14,3347.25) -1556.03,3340.36 -1556.03,3328.76 R85.2@-1537.68,3310.42
MCU_PGA3_IN_P: C78.1 R87.2 U1.29 | length 1339
  Top Signal w5.91: v1(-1574.73,3347.25) -1567.84,3354.14 -1567.84,3366.31 -1554.37,3379.78 -1530.28,3379.78 -1518.64,3368.14 -1518.64,3328.01 -1540.49,3306.16 -1540.49,2780.67 -1614.04,2707.12 -1614.04,2421.02 -1574.49,2381.47 -1544.67,2381.47 -1511.27,2414.87 -1511.27,2420.44 U1.29@-1486.91,2444.8
  Bottom Signal w5.91: C78.1@-1586.36,3387.25 -1567.84,3368.73 -1567.84,3354.14 v1(-1574.73,3347.25) -1567.84,3340.36 -1567.84,3328.76 R87.2@-1586.18,3310.42
MCU_RXD: J101.2 U9.6 | length 291.7
  Top Signal w5: J101.2@-980.04,4225.55 -980.04,4072.55 -960.56,4053.07 U9.6@-960.56,3941.88
MCU_TCK: J101.8 U1.60 | length 2304.1
  Top Signal w5: v1(-1344.04,3109.55) -1319.41,3134.18 -1319.41,4186.18 J101.8@-1280.04,4225.55 ; v1(-1050.04,2286.76) -1050.04,2287.42 -1034.64,2302.82 -1005.3,2302.82 U1.60@-980.24,2277.77
  Bottom Signal w5: v1(-1344.04,3109.55) -1385.04,3109.55 -1461.85,3032.74 -1461.85,2905.08 -1315.14,2758.37 -1315.14,2537.97 -1066.36,2289.19 -1052.47,2289.19 v1(-1050.04,2286.76)
MCU_TDI: J101.12 R44.2 R111.1 | length 2083.1
  Top Signal w5: J101.12@-1480.04,4225.55 -1342.57,4088.08 -1342.57,3153.49 -1384.04,3112.02 v1(-1384.04,3035.55)
  Bottom Signal w5: v1(-1384.04,3035.55) -1423.57,2996.02 -1423.57,2915.82 -1282.42,2774.67 -1282.42,2661.55 -1093.38,2472.51 -1055.05,2472.51 -1010.88,2428.34 R44.2@-1010.88,2426.39
MCU_TDO: J101.10 R45.2 R112.1 | length 2125.4
  Top Signal w5: J101.10@-1380.04,4225.55 -1331.66,4177.18 -1331.66,3148.98 -1361.3,3119.34 -1361.3,3086.29 v1(-1362.04,3085.55)
  Bottom Signal w5: v1(-1362.04,3085.55) -1383.04,3085.55 -1448.42,3020.17 -1448.42,2907.08 -1304.23,2762.88 -1304.23,2542.49 -1163.24,2401.5 -1124.9,2401.5 -1080.42,2357.01 R45.2@-1080.42,2355.72
MCU_TMS: J101.6 R10.1 U1.62 | length 2263.6
  Top Signal w5: v1(-1361.63,3054.55) -1308.5,3107.68 -1308.5,4097.09 J101.6@-1180.04,4225.55 ; v1(-995.04,2348.24) U1.62@-952.4,2305.61
  Bottom Signal w5: v1(-1361.63,3054.55) -1391.04,3054.55 -1436.04,3009.55 -1436.04,2910.11 -1293.33,2767.4 -1293.33,2612.53 -1119.08,2438.29 R10.1@-1090.49,2438.29 -1084.9,2438.29 -995.04,2348.43 v1(-995.04,2348.24)
MCU_TXD: J101.4 U9.10 | length 300.5
  Top Signal w5: J101.4@-1080.04,4225.55 -1080.04,4162.55 -1039.3,4121.81 U9.10@-1039.3,3941.88
MCU_VREFHI: C24.1 J15.1 U1.24 U1.25 | length 837
  Top Signal w11.81: U1.25@-1528.67,2575.64 -1551.88,2598.86 -1551.88,2618.55 v2(-1547.81,2618.55) -1543.74,2618.55 U1.24@-1514.75,2589.56
  Top Signal w19.68: J15.1@-1850.04,2125.55 -1726.54,2249.05 v2(-1726.54,2573.59)
  Bottom Signal w19.68: v2(-1726.54,2573.59) v2(-1572.44,2573.59) C24.1@-1539.04,2573.59 -1539.04,2609.78 v2(-1547.81,2618.55)
NetC7_1: C7.1 U10.3 | length 64.8
  Bottom Signal w7.87: C7.1@-558.04,4255.55 -528.72,4226.24 U10.3@-505.36,4226.24
NetC50_2: C50.2 R62.2 U2.96 | length 137.4
  Top Signal w7.87: U2.96@-296.69,5294.65 -239.96,5294.65 C50.2@-232.83,5301.77 -232.83,5344.21 -223.03,5354.02 R62.2@-208.74,5354.02
NetC59_1: C59.1 C60.2 C61.1 U2.87 U2.115 | length 719.9
  Top Signal w10: v1(-639.21,5315.04) U2.115@-639.21,5353.7 ; v1(-334.76,5152.32) U2.87@-296.1,5152.32
  Bottom Signal w11.81: C61.1@-697.43,5286.11 -695.76,5284.44 -678.78,5284.44 -653.91,5284.44 -639.25,5299.09 -639.25,5310.87 -639.21,5310.91 v1(-639.21,5315.04) ; C59.1@-360,5154.45 -355.14,5149.59 -339.1,5149.59 -336.98,5151.7 v1@-335.38,5151.7
  Bottom Signal w19.68: C61.1@-697.43,5286.11 -695.46,5288.08 -695.46,5299.06 -656.14,5338.38 -388.89,5338.38 -356.37,5305.86 -356.37,5162.01 -358.03,5160.35 -358.03,5156.42 C59.1@-359.02,5155.43
NetC62_1: C62.1 U2.88 Y1.1 | length 261.1
  Top Signal w7.87: U2.88@-296.69,5168.66 -232.91,5168.66 -202.04,5137.8 -188.28,5151.55 -113.8,5151.55 Y1.1@-71.54,5109.3
NetC63_1: C63.1 U2.89 Y1.3 | length 166.9
  Top Signal w7.87: U2.89@-296.69,5184.41 -213.54,5184.41 -202.04,5195.91 Y1.3@-134.54,5195.91
NetC66_2: C66.2 R70.1 U2.68 | length 223.5
  Top Signal w7.87: U2.68@-296.69,4853.7 -261.02,4853.7 -235.91,4828.58 -235.91,4744.57 -223.86,4732.52 R70.1@-206.38,4732.52
  Bottom Signal w11.81: C66.2@-285.51,4850.28 -257.8,4850.28 v1(-253.54,4846.02)
NetC81_2: C81.2 J8/J6.79 R50.2 | length 161.7
  Top Signal w7.87: R50.2@-438.94,1423.5 -434.88,1427.57 -434.88,1469.13 C81.2@-438.94,1473.19 -397.68,1473.19 J8/J6.79@-350.04,1425.55
NetC82_2: C82.2 J8/J6.80 R49.2 | length 166.1
  Top Signal w5: R49.2@-437.8,1531.3 R49.2@-432.05,1525.55
  Top Signal w7.87: C82.2@-438.92,1578.5 C82.2@-437.8,1578.5 ; R49.2@-437.8,1531.3 C82.2@-437.8,1578.5 ; J8/J6.80@-350.04,1525.55 -402.99,1578.5 C82.2@-437.8,1578.5
NetC83_2: C83.2 J4/J2.39 R9.2 | length 154.9
  Top Signal w5: C83.2@-441.34,3968.43 -441.46,3968.31 R9.2@-441.46,3918.27 -434.17,3925.55 J4/J2.39@-350.04,3925.55 J4/J2.39@-357.32,3918.27
NetC84_2: C84.2 J4/J2.40 R8.2 | length 145.5
  Top Signal w5: C84.2@-441.34,4074.49 -441.46,4074.37 R8.2@-441.46,4021.02 -436.93,4025.55 -354.57,4025.55 J4/J2.40@-352.3,4023.29
NetC102_1: C102.1 R101.1 R102.2 U101.2 | length 174.1
  Top Signal w20: U101.2@-2046.65,4418.27 -1970.59,4418.27 ; R101.1@-1968.66,4395.55 R102.2@-1968.66,4493.55
NetC106_2: C106.2 U3.3 U3.4 U3.5 | length 348.3
  Top Signal w19.68: U3.5@-1629.53,4920.55 -1702.68,4920.55 -1717.6,4935.47 -1717.6,4971.18 ; U3.4@-1629.53,4970.55 -1716.97,4970.55 -1717.6,4971.18 ; U3.3@-1629.53,5020.55 -1629.53,5018.87 -1679.4,5018.87 -1692.09,5006.18 C106.2@-1717.6,5006.18 -1717.6,4971.18
NetJ5/J7_41: J5/J7.41 JP8.3 | length 200
  Top Signal w50: J5/J7.41@-2050.04,1525.55 JP8.3@-2050.04,1725.55
NetJ5/J7_61: J5/J7.61 JP8.4 | length 200
  Top Signal w50: J5/J7.61@-1950.04,1525.55 JP8.4@-1950.04,1725.55
NetJ14_1: J14.1 R79.2 U15.7 | length 366.9
  Top Signal w7.87: U15.7@-632.44,317.95 -632.44,231.55 -632.44,195.95 -587.47,150.98 -461.22,150.98 -450.04,139.8 J14.1@-450.04,100.55
NetJ14_2: J14.2 JP9.1 U15.6 | length 634.3
  Top Signal w7.87: U15.6@-682.44,325.55 -682.44,317.95 -682.44,217.95 -565.04,100.55 J14.2@-550.04,100.55 ; U15.6@-680.04,317.95 -680.04,325.55 -680.04,357.55 -660.04,377.55 -443.04,377.55 JP9.1@-400.04,420.55
NetJ16_2: J16.2 L4.1 U18.A1 U18.C1 | length 760
  Top Signal w9.06: L4.1@-1845.04,1885.55 -1845.04,1925.74 -1831.23,1939.55 -1738.04,1939.55 -1715.38,1916.9 U18.A1@-1715.38,1901.5 ; -1715.38,1847.21 U18.C1@-1715.38,1870
  Top Signal w31.5: J16.2@-2050.04,2125.55 -1994.04,2125.55 -1938.04,2069.55 -1938.04,1973.55 L4.1@-1850.04,1885.55 ; L4.1@-1845.04,1885.55 -1845.04,1839.55 -1827.04,1821.55 -1730.04,1821.55 -1721.04,1830.55
NetJP9_2: JP9.2 R79.1 | length 206.4
  Top Signal w7.87: R79.1@-569.54,231.55 -489.04,231.55 JP9.2@-400.04,320.55
NetL4_2: L4.2 U18.B1 | length 49.5
  Top Signal w9.06: L4.2@-1764.84,1885.75 U18.B1@-1715.38,1885.75
NetLED0_2: LED0.2 R105.1 | length 54.7
  Top Signal w11.81: R105.1@-1680.04,4535.55 LED0.2@-1625.38,4535.55
NetLED1_2: LED1.2 R3.1 | length 69.3
  Top Signal w8: R3.1@-1546.65,4041.14 -1537.68,4032.17 LED1.2@-1537.68,3975.55
NetLED2_1: LED2.1 R63.1 | length 57
  Top Signal w7.87: R63.1@-1015.04,5267.17 LED2.1@-1015.04,5324.21
NetLED3_1: LED3.1 R64.1 | length 57
  Top Signal w7.87: R64.1@-1100.04,5267.17 LED3.1@-1100.04,5324.21
NetLED4_1: LED4.1 U7.6 | length 91.3
  Top Signal w8: LED4.1@-750.04,3880.55 -745.4,3875.91 U7.6@-745.4,3791.21
NetLED4_2: LED4.2 R28.1 | length 80.9
  Top Signal w8: R28.1@-818.19,3932.48 -780.79,3932.48 LED4.2@-750.04,3963.23
NetLED5_1: LED5.1 R29.1 | length 74.9
  Top Signal w8: LED5.1@-669.41,3957.8 -644.09,3932.48 R29.1@-605.04,3932.48
NetLED5_2: LED5.2 U7.4 | length 83.4
  Top Signal w8: U7.4@-670.6,3791.21 -670.6,3870.99 LED5.2@-668,3873.58
NetLED6_2: LED6.2 R43.1 | length 69.9
  Top Signal w11.81: LED6.2@-1989.21,4219.33 R43.1@-1919.29,4219.33
NetLED7_2: LED7.2 R7.1 | length 76.2
  Top Signal w30: R7.1@-2023.35,4988.9 -2023.35,4927.09 LED7.2@-2013.19,4916.93
NetR1_1: R1.1 U3.11 | length 93
  Top Signal w10.63: U3.11@-1245.67,4870.55 -1225.79,4870.55 -1209.67,4854.43 -1184.74,4854.43 R1.1@-1166.77,4872.4
NetR2_1: R2.1 U3.10 | length 94.8
  Top Signal w10.63: U3.10@-1247.44,4823.39 -1218.7,4823.39 -1204.19,4837.89 -1184.04,4837.89 R2.1@-1166.06,4819.92
NetR5_2: R5.2 U10.4 | length 100.7
  Top Signal w5: v1(-396.04,4226.24) -358.4,4226.24 R5.2@-357.72,4225.55
  Bottom Signal w5: U10.4@-458.12,4226.24 v1(-396.04,4226.24)
NetR30_1: R30.1 R34.2 U7.1 | length 129.3
  Top Signal w8: R30.1@-808,3743.46 R34.2@-808,3678.57 -803.63,3682.94 U7.1@-745.4,3682.94
NetR31_1: R31.1 R35.2 U7.3 | length 128.7
  Top Signal w8: U7.3@-670.6,3682.94 -613.37,3682.94 R35.2@-609,3678.57 -608,3679.57 R31.1@-608,3743.46
NetR38_2: R38.2 S3.5 | length 90.7
  Top Signal w5: S3.5@-1022.6,1758.5 -1022.44,1758.66 v1(-979.88,1758.66)
  Bottom Signal w5: R38.2@-1027.32,1759.72 -1026.26,1758.66 v1(-979.88,1758.66)
NetR39_1: R39.1 S3.2 | length 84
  Top Signal w5: S3.2@-876.93,1758.5 -876.06,1759.37 v1(-831.1,1759.37)
  Bottom Signal w5: R39.1@-868.82,1759.72 -868.46,1759.37 v1(-831.1,1759.37)
NetR47_1: R47.1 R52.2 U13.2 | length 148.7
  Top Signal w11.81: U13.2@-1038.15,692.99 -1038.15,751.06 R47.1@-1014.92,774.29 -1014.92,831.3 R52.2@-1014.41,831.81
NetR48_1: R48.1 R53.1 U13.22 | length 356.1
  Top Signal w11.81: U13.22@-1063.74,460.71 -1063.74,428.5 -1050,414.76 -966.5,414.76 -929.78,451.48 R53.1@-929.78,555.55 R48.1@-929.78,620.55
NetR63_2: R63.2 U2.3 | length 130
  Top Signal w7.87: R63.2@-1015.04,5219.92 -989.17,5219.92 -945.94,5263.15 U2.3@-902.99,5263.15
NetR64_2: R64.2 U2.4 | length 251.2
  Top Signal w7.87: R64.2@-1100.04,5219.92 -1100.04,5196.06 -1089.09,5185.12 -994.53,5185.12 -932.24,5247.4 U2.4@-902.99,5247.4
NetR65_1: R65.1 R67.2 U2.70 | length 146.6
  Top Signal w7.87: U2.70@-296.69,4885.2 -209.96,4885.2 R65.1@-206.02,4881.26 R67.2@-206.02,4935.55
NetR68_2: R68.2 U2.59 | length 73
  Top Signal w7.87: R68.2@-443.43,4678.07 -434.49,4687.01 U2.59@-434.49,4747.4
NetR82_2: R82.2 R83.1 U1.73 | length 461.5
  Top Signal w5: U1.73@-799.29,2458.72 -766.12,2425.55 v1(-766.02,2425.55)
  Bottom Signal w5: R82.2@-1012.56,2510.22 -1012.56,2510.06 R83.1@-966.92,2464.43 -966.92,2468.95 -875.32,2560.55 -834.95,2560.55 -751.81,2477.42 -751.81,2441.78 -766.02,2427.57 v1(-766.02,2425.55)
NetR103_2: R103.2 U3.6 | length 75.8
  Top Signal w7.87: R103.2@-1704.96,4869.76 -1704.17,4870.55 U3.6@-1629.53,4870.55
NetR104_2: R104.2 U3.7 | length 76.6
  Top Signal w7.87: R104.2@-1704.96,4823.43 -1702.09,4820.55 U3.7@-1629.53,4820.55
NetR106_1: R106.1 Y2.3 | length 106.4
  Top Signal w6: Y2.3@-592.48,2288.26 -581.67,2299.07 R106.1@-490.52,2299.07
PGA1_IN_N: J10.4 U17.1 | length 971.1
  Bottom Signal w5.91: J10.4@-2050.04,2425.55 -2050.04,2457.74 -2059.04,2466.74 -2095.17,2466.74 -2107.22,2478.8 -2107.22,2575.13 -2090.46,2591.89 -2027.6,2591.89 -1936.85,2682.64 -1936.85,3041.44 -1834.87,3143.43 -1834.87,3159.95 -1841.76,3166.84 U17.1@-1841.76,3199.32
PGA1_IN_N_BP: R107.1 U17.13 | length 85.3
  Bottom Signal w5.91: R107.1@-1567.85,2888.83 R107.1@-1560.26,2896.41 U17.13@-1560.26,2970.98
PGA1_IN_P: J10.1 U17.2 | length 955.8
  Bottom Signal w5.91: J10.1@-2050.04,2525.55 -2050.04,2490.24 -2061.73,2478.55 -2090.27,2478.55 -2095.41,2483.69 -2095.41,2570.24 -2085.57,2580.08 -2022.71,2580.08 -1925.04,2677.75 -1925.04,3036.55 -1823.06,3138.54 -1823.06,3159.95 -1816.17,3166.84 U17.2@-1816.17,3199.32
PGA1_IN_P_BP: J1/J3.27 U17.11 | length 572.1
  Top Signal w5.91: J1/J3.27@-1950.04,3425.55 -1893.04,3368.55 -1893.04,3300.58 -1727.26,3134.8 v1(-1614.61,3134.8)
  Bottom Signal w5.91: v1(-1614.61,3134.8) -1585.85,3163.56 U17.11@-1585.85,3199.32
PGA2_IN_N: J10.5 U17.21 | length 891.8
  Bottom Signal w5.91: J10.5@-1950.04,2425.55 -1950.04,2466.19 -1953.5,2469.65 -1975.9,2469.65 -2005.94,2499.69 -2005.94,2552.59 -1896.85,2661.68 -1896.85,3030.92 -1868.75,3059.02 -1810.41,3059.02 -1788.82,3037.43 -1788.82,3023.33 -1770.89,3005.4 -1770.89,2976.88 U17.21@-1764.98,2970.98
PGA2_IN_N_BP: R108.1 U17.17 | length 83.2
  Bottom Signal w5.91: R108.1@-1665.19,2888.83 -1662.62,2891.4 U17.17@-1662.62,2970.98
PGA2_IN_P: J10.2 U17.23 | length 829.6
  Bottom Signal w5.91: J10.2@-1950.04,2525.55 -1950.04,2484.92 -1953.5,2481.46 -1971,2481.46 -1994.13,2504.59 -1994.13,2547.7 -1885.04,2656.79 -1885.04,3026.03 -1863.86,3047.21 -1815.3,3047.21 -1800.63,3032.54 -1800.63,3021.59 -1810.26,3011.96 -1810.26,2976.88 U17.23@-1816.17,2970.98
PGA2_IN_P_BP: J1/J3.28 U17.15 | length 504.8
  Top Signal w5.91: J1/J3.28@-1950.04,3325.55 v1(-1762.6,3138.11)
  Bottom Signal w5.91: v1(-1762.6,3138.11) -1745.6,3138.11 -1611.44,3003.95 U17.15@-1611.44,2970.98
PGA3_IN_N: J10.6 U17.22 | length 650.7
  Bottom Signal w5.91: J10.6@-1850.04,2425.55 -1850.04,2466.19 -1853.5,2469.65 -1873.93,2469.65 -1903.78,2499.5 -1903.78,2567.61 -1761.42,2709.97 -1761.42,2903.66 -1787.42,2929.67 -1787.42,2967.83 U17.22@-1790.57,2970.98
PGA3_IN_N_BP: J1/J3.2 U17.16 | length 1253.5
  Top Signal w5.91: J1/J3.2@-2050.04,3925.55 -2099.04,3876.55 -2099.04,3397.55 -2080.04,3378.55 -2017.19,3378.55 -2003.04,3364.4 -2003.04,3286.55 -1987.04,3270.55 -1939.36,3270.55 -1788.54,3119.73 v1(-1788.54,3119.55)
  Bottom Signal w5.91: v1(-1788.54,3119.55) -1750.04,3119.55 -1637.03,3006.54 U17.16@-1637.03,2970.98
PGA3_IN_P: J10.3 U17.19 | length 633.9
  Bottom Signal w5.91: J10.3@-1850.04,2525.55 -1850.04,2484.92 -1853.5,2481.46 -1869.04,2481.46 -1891.97,2504.39 -1891.97,2562.71 -1749.61,2705.07 -1749.61,2900.34 -1718.84,2931.11 -1718.84,2965.94 U17.19@-1713.8,2970.98
PGA3_IN_P_BP: J1/J3.29 U17.18 | length 397.4
  Top Signal w5.91: J1/J3.29@-1950.04,3225.55 -1945.54,3225.55 v1(-1818.54,3098.55)
  Bottom Signal w5.91: v1(-1818.54,3098.55) -1766.04,3098.55 -1688.21,3020.72 U17.18@-1688.21,2970.98 U17.18@-1687.54,2971.65
PGA_SEL: S6.2 U17.14 U17.24 | length 508.2
  Top Signal w5.91: v1(-1841.76,2925.55) -1801.66,2925.55 -1785.04,2908.93 S6.2@-1785.04,2848.56 ; v1(-1840.54,3016.55) v1(-1593.35,3016.59)
  Bottom Signal w5.91: v1(-1841.76,2925.55) U17.24@-1841.76,2970.98 -1841.76,3015.33 v1(-1840.54,3016.55) ; U17.14@-1585.85,2970.98 v1@-1585.85,3016.55
QEP3_SEL: S5.2 U11.9 U11.10 U11.11 | length 490.9
  Top Signal w7.87: U11.11@-1236.75,1156.65 -1186.24,1156.65 -1177.91,1164.98 -1177.91,1182.24 ; U11.10@-1236.75,1182.24 -1177.91,1182.24 ; U11.9@-1236.75,1207.83 -1177.91,1207.83 ; S5.2@-1226.94,1455.6 -1226.94,1298.64 -1177.91,1249.61 -1177.91,1207.83 ; -1177.91,1182.24 -1177.91,1207.83
SCI_SEL1: S2.2 U6.1 U6.5 U9.1 U9.5 | length 952.1
  Top Signal w11.81: U6.5@-1413.54,3839.49 -1373.31,3839.49 -1371.61,3837.8 ; U6.1@-1413.54,3918.23 -1384.97,3918.23 -1371.5,3904.76 v1(-1371.5,3766.68) ; v1(-1177.62,3766.55) -1177.49,3766.68 -1160.24,3766.68 ; S2.2@-1071.81,3606.87 -1128.47,3606.87 -1160.24,3638.63 -1160.24,3766.68 ; U9.5@-960.56,3766.68 -960.56,3805.07 -970.04,3814.55 -1027.16,3814.55 -1039.3,3802.41 U9.1@-1039.3,3766.68 -1160.24,3766.68
  Bottom Signal w11.81: v1(-1371.5,3766.68) -1371.36,3766.55 v1(-1177.62,3766.55)
SCI_SEL2: S2.5 U8.1 U8.5 | length 3186.2
  Top Signal w5: v1(-1008.64,3606.87) -1008.4,3606.63 -1008.4,3478.56 -977.39,3447.55 -802.31,3447.55 -754.3,3495.57 -669.7,3495.57 -642.78,3468.65 -642.78,2904.26 -707.72,2839.31 v1(-707.72,2802.92) ; S2.5@-926.14,3606.87 v1(-866.1,3606.87) ; U8.1@-803.95,1382.7 -765.68,1382.7 -760.18,1388.19 -760.18,1461.44 ; U8.5@-803.95,1461.44 -760.18,1461.44 ; v1(-765.04,1586.55) -760.18,1581.7 -760.18,1461.45
  Bottom Signal w5: v1(-1008.64,3606.87) v1(-866.1,3606.87) ; v1(-765.04,1586.55) -681.62,1586.55 -662.78,1605.4 -662.78,2122.82 -497.85,2287.74 -497.85,2552.52 -672.59,2727.25 -672.59,2767.78 v1(-707.72,2802.92)
USB_CC1: R88.2 U16.4 U16.7 USB101.A5 | length 317.1
  Top Signal w6: R88.2@-1899.66,4976.93 -1899.66,5014.95 -1890.98,5023.63 -1821.65,5023.63 -1775.51,5069.77 -1775.51,5162.36 -1794.21,5181.06 USB101.A5@-1794.21,5194.25
USB_CC2: R89.2 U16.5 U16.6 USB101.B5 | length 562.6
  Top Signal w6: R89.2@-1841.18,4981.5 -1841.18,5004.45 -1835,5010.63 -1816.96,5010.63 -1755.83,5071.76 v1@-1755.83,5147.64
  Top Signal w7.87: v4(-1849.88,5234.13) -1844.33,5239.69 USB101.B5@-1844.33,5265.12
  GND w7.87: v4(-1849.88,5234.13) -1878.27,5234.13 -1920.98,5191.42 -1920.98,5146.02 -1901.26,5126.3 -1779.21,5126.3 v1(-1755.77,5149.74)
USB_D_N: R103.1 U16.1 U16.10 USB101.A7 USB101.B7 | length 714.4
  Top Signal w10.63: v1(-1838.66,5071.5) -1834.49,5075.67 USB101.A7@-1834.49,5202.13 ; USB101.B7@-1804.96,5265.12 -1804.96,5242.77 v4(-1801.54,5239.34) ; v1(-1789.33,4861.46) -1783.48,4855.61 -1766.36,4855.61 R103.1@-1752.2,4869.76
  Bottom Signal w10.63: v1(-1838.66,5071.5) -1832.85,5077.3 -1832.85,5082.78 -1840.24,5090.16 -1855.59,5090.16 -1863.39,5082.36 -1863.39,4874.57 -1844.06,4855.24 -1796.18,4855.24 ; v4(-1837.17,5171.54) -1833.19,5175.51 -1833.19,5190.75 -1815.79,5208.15 -1783.15,5208.15 -1775.83,5215.47 -1775.83,5247.2 -1783.03,5254.41 -1801.26,5254.41 -1805.55,5250.12 -1805.55,5243.36 v4(-1801.54,5239.34) ; v1@-1795.55,4855.24 v1(-1789.33,4861.46)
